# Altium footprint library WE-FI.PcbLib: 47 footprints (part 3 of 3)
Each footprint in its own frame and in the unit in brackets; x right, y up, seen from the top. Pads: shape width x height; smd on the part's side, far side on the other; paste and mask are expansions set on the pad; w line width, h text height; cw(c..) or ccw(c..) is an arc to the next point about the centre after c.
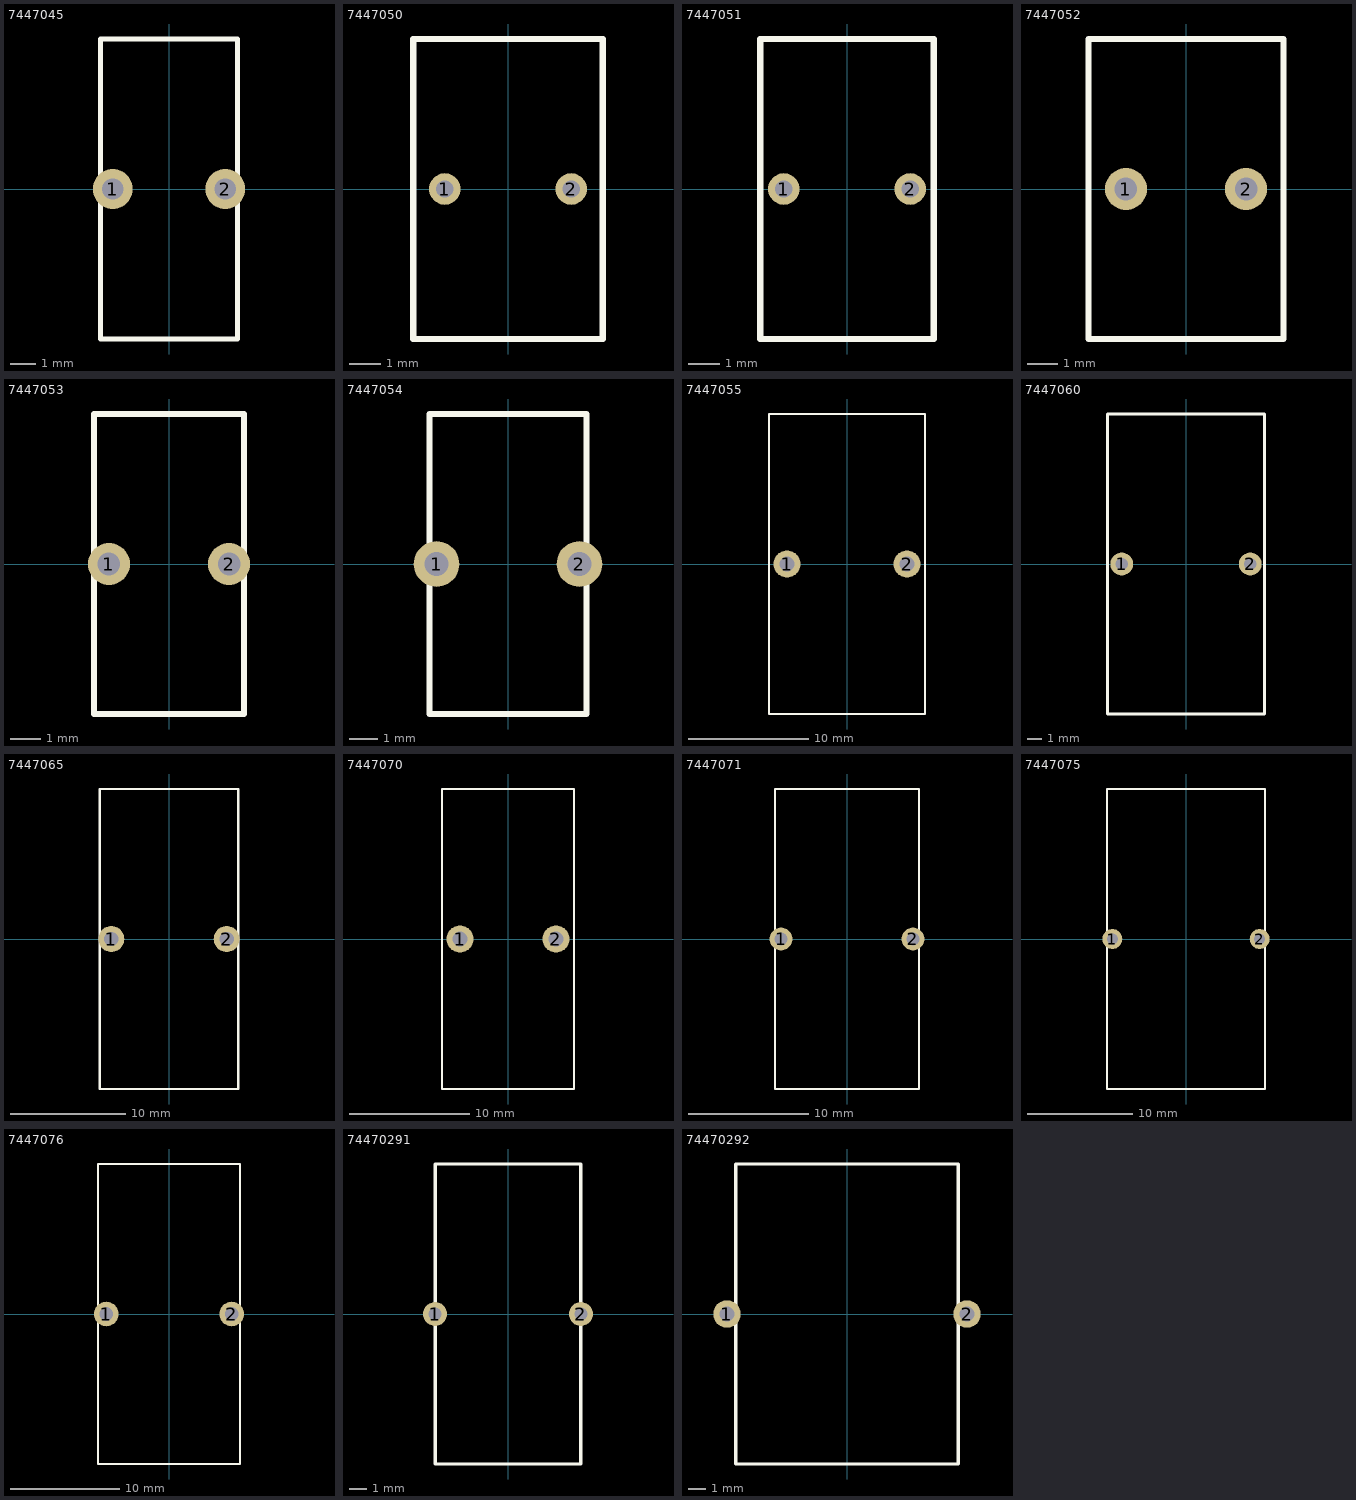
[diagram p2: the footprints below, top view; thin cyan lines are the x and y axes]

## 7447045 [mm] "Body 12x5.5mm, 2 leads"
height 12
pads (2):
  round 1.6 hole 0.85: 1(-2.25,0) 2(2.25,0)
Top Overlay:
  lines w0.2: -2.75,-6 -2.75,6 2.75,6 2.75,-6 -2.75,-6
3D body: height 13.62, standoff -14, extent -3.37,-6.618 3.37,6.62

## 7447050 [mm] "Body 9.5x6mm, 2 leads"
height 9.5
pads (2):
  round 1 hole 0.55: 1(-2,0) 2(2,0)
Top Overlay:
  lines w0.2: -3,-4.75 -3,4.75 3,4.75 3,-4.75 -3,-4.75
3D body: height 9.75, standoff -14.4, extent -2.85,-4.749 2.85,4.749

## 7447051 [mm] "Body 9.5x5.5mm, 2 leads"
height 9.5
pads (2):
  round 1 hole 0.55: 1(-2,0) 2(2,0)
Top Overlay:
  lines w0.2: -2.75,-4.75 2.75,-4.75 2.75,4.75 -2.75,4.75 -2.75,-4.75
3D body: height 10.07, standoff -14.75, extent -2.57,-5.049 2.57,5.049

## 7447052 [mm] "Body 10x6.5mm, 2 leads"
height 10
pads (2):
  round 1.4 hole 0.75: 1(-2,0) 2(2,0)
Top Overlay:
  lines w0.2: -3.25,-5 3.25,-5 3.25,5 -3.25,5 -3.25,-5
3D body: height 10.98, standoff -14.5, extent -3.26,-5.502 3.26,5.502

## 7447053 [mm] "Body 10x5mm, 2 leads"
height 10
pads (2):
  round 1.4 hole 0.75: 1(-2,0) 2(2,0)
Top Overlay:
  lines w0.2: -2.5,-5 2.5,-5 2.5,5 -2.5,5 -2.5,-5
3D body: height 10.99, standoff -14.5, extent -3.01,-5.503 3.01,5.502

## 7447054 [mm] "Body 10.5x5.5mm, 2 leads"
height 10.5
pads (2):
  round 1.6 hole 0.85: 1(-2.5,0) 2(2.5,0)
Top Overlay:
  lines w0.2: -2.75,-5.25 -2.75,5.25 2.75,5.25 2.75,-5.25 -2.75,-5.25
3D body: height 11.72, standoff -14.35, extent -3.371,-5.857 3.37,5.857

## 7447055 [mm] "Body 25x13mm, 2 leads"
height 25
pads (2):
  round 2.25 hole 1.25: 1(-5,0) 2(5,0)
Top Overlay:
  lines w0.2: -6.5,-12.5 -6.5,12.5 6.5,12.5 6.5,-12.5 -6.5,-12.5
3D body: height 25.48, standoff -14.5, extent -4.75,-12.494 4.75,12.493

## 7447060 [mm] "Body 21x11mm, 2 leads"
height 21
pads (2):
  round 1.6 hole 0.85: 1(-4.5,0) 2(4.5,0)
Top Overlay:
  lines w0.2: -5.5,-10.5 -5.5,10.5 5.5,10.5 5.5,-10.5 -5.5,-10.5
3D body: height 23.1, standoff -23.5, extent -6.12,-11.114 6.12,11.115

## 7447065 [mm] "Body 26x12mm, 2 leads"
height 26
pads (2):
  round 2.25 hole 1.25: 1(-5,0) 2(5,0)
Top Overlay:
  lines w0.2: -6,-13 6,-13 6,13 -6,13 -6,-13
3D body: height 25.48, standoff -14.5, extent -4.75,-12.494 4.75,12.493

## 7447070 [mm] "Body 25x11mm, 2 leads"
height 25
pads (2):
  round 2.25 hole 1.25: 1(-4,0) 2(4,0)
Top Overlay:
  lines w0.2: -5.5,-12.5 -5.5,12.5 5.5,12.5 5.5,-12.5 -5.5,-12.5
3D body: height 27.48, standoff -13.5, extent -6.52,-13.508 6.52,13.509

## 7447071 [mm] "Body 25x12mm, 2 leads"
height 25
pads (2):
  round 1.9 hole 1.05: 1(-5.5,0) 2(5.5,0)
Top Overlay:
  lines w0.2: -6,-12.5 -6,12.5 6,12.5 6,-12.5 -6,-12.5
3D body: height 27.3, standoff -23.5, extent -6.82,-13.312 6.82,13.312

## 7447075 [mm] "Body 28.5x15mm, 2 leads"
height 28.5
pads (2):
  round 1.9 hole 1.05: 1(-7,0) 2(7,0)
Top Overlay:
  lines w0.2: -7.5,-14.25 7.5,-14.25 7.5,14.25 -7.5,14.25 -7.5,-14.25
3D body: height 30.65, standoff -23.75, extent -8.42,-15.164 8.42,15.163

## 7447076 [mm] "Body 27.5x13mm, 2 leads"
height 27.5
pads (2):
  round 2.25 hole 1.25: 1(-5.75,0) 2(5.75,0)
Top Overlay:
  lines w0.2: -6.5,-13.75 -6.5,13.75 6.5,13.75 6.5,-13.75 -6.5,-13.75
3D body: height 28.22, standoff -11.95, extent -6.5,-13.741 6.5,13.744

## 74470291 [mm] "Body 17.5x8.5mm, 2 leads"
height 17.5
pads (2):
  round 1.4 hole 0.75: 1(-4.25,0) 2(4.25,0)
Top Overlay:
  lines w0.2: -4.25,-8.75 4.25,-8.75 4.25,8.75 -4.25,8.75 -4.25,-8.75
3D body: height 18.8, standoff -24.25, extent -4.82,-9.315 4.82,9.315

## 74470292 [mm] "Body 17.5x13mm, 2 leads"
height 17.5
pads (2):
  round 1.6 hole 0.85: 1(-7,0) 2(7,0)
Top Overlay:
  lines w0.2: -6.5,-8.75 -6.5,8.75 6.5,8.75 6.5,-8.75 -6.5,-8.75
3D body: height 18.85, standoff -19.25, extent -7.12,-9.365 7.12,9.365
